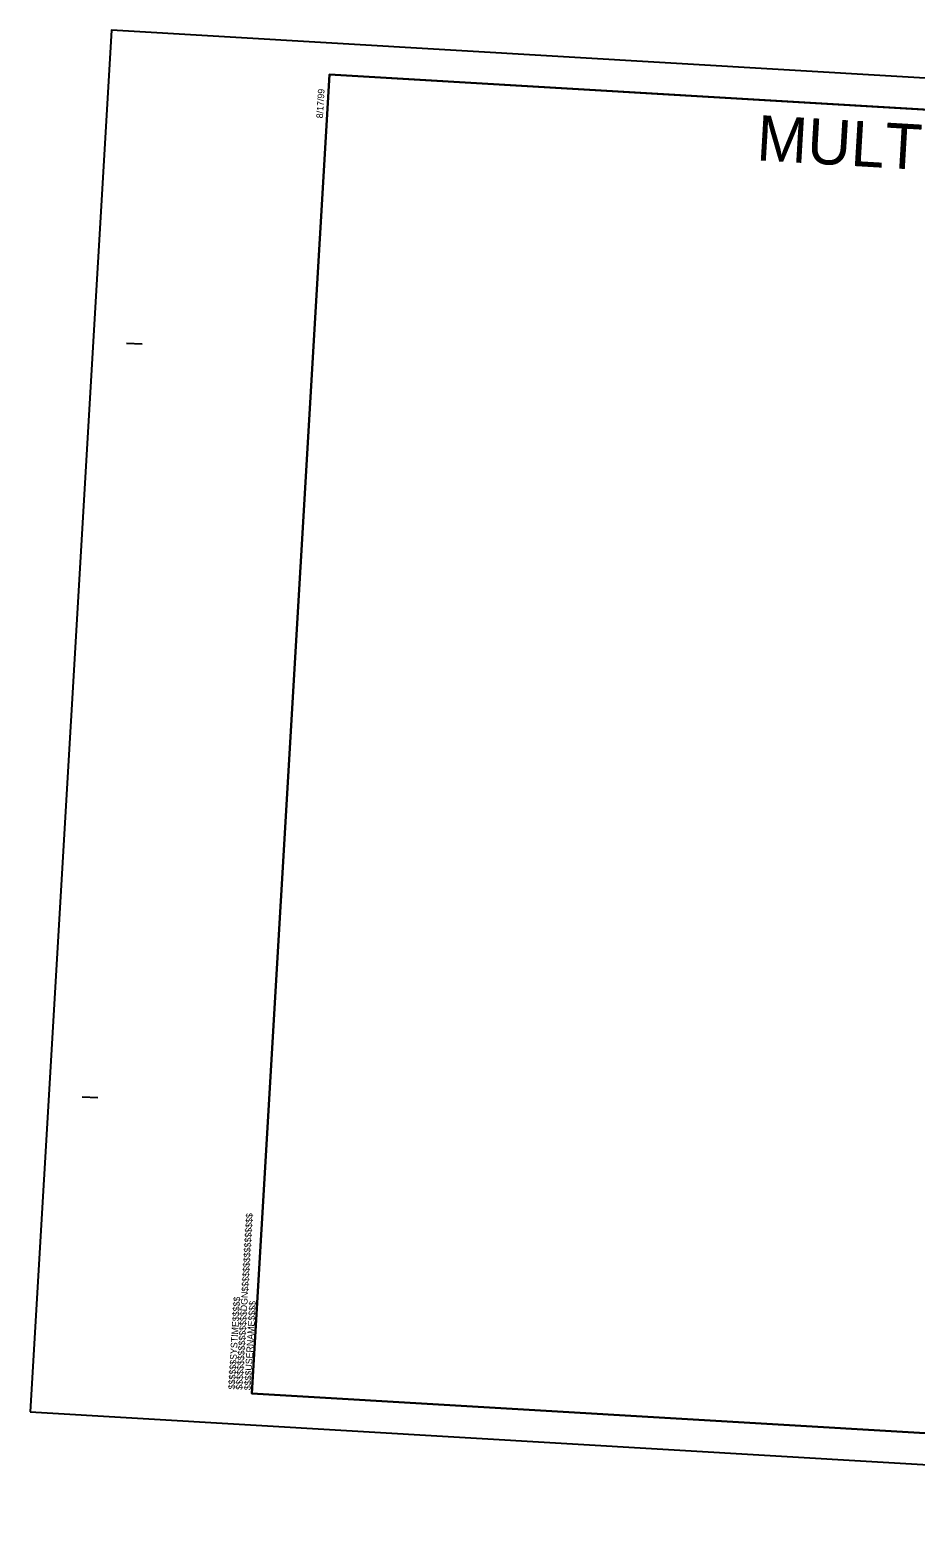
# Model space of a CAD drawing. Extents: x 2011701 to 2013463, y 444552 to 445750.
# Drawn here: x 2011701 to 2012405, y 444552 to 445750 of the extents above; entities that cross this region are included whole.
import ezdxf

# ---------------------------------------------------------------- set-up
doc = ezdxf.new("R2010")
doc.units = 0
for name, color, linetype in [('Prop Dimension', 7, 'Continuous'), ('Sheet Block System Information CELL', 7, 'Continuous'), ('Sheet Clip Boundary CELL', 7, 'Continuous'), ('Sheet Plan And Profile CELL', 7, 'Continuous'), ('Sheet Plot Border Outside CELL', 7, 'Continuous')]:
    doc.layers.add(name, color=color, linetype=linetype)

msp = doc.modelspace()

# ---------------------------------------------------------------- linework, layer by layer
at = {"layer": 'Sheet Block System Information CELL'}
msp.add_line((2011877.5, 444666.9), (2011877.5, 444666.9), dxfattribs=at)
at = {"layer": 'Sheet Clip Boundary CELL'}
msp.add_lwpolyline([(2011939.3, 445715.1), (2013237, 445638.6), (2013226.3, 445456.9), (2013426, 445445.2), (2013374.9, 444578.7), (2011877.5, 444666.9)], close=True, dxfattribs=at)
at = {"layer": 'Sheet Plan And Profile CELL'}
for p, q in [((2011778, 445501.7), (2011790.5, 445501)), ((2011742.7, 444902.8), (2011755.2, 444902.1)), ((2011901.8, 444665.5), (2011901.8, 444665.5)), ((2011901.8, 444665.5), (2011901.8, 444665.5)), ((2011901.8, 444665.5), (2011901.8, 444665.5)), ((2011901.8, 444665.5), (2011901.8, 444665.5)), ((2011901.8, 444665.5), (2011901.8, 444665.5))]:
    msp.add_line(p, q, dxfattribs=at)
msp.add_lwpolyline([(2013436.7, 445626.9), (2011939.3, 445715.1), (2011877.5, 444666.9), (2013374.9, 444578.7)], close=True, dxfattribs=at)
at = {"layer": 'Sheet Plot Border Outside CELL'}
msp.add_lwpolyline([(2011701.4, 444652.3), (2013398.4, 444552.2), (2013463.2, 445650.3), (2011766.1, 445750.4)], close=True, dxfattribs=at)

# ---------------------------------------------------------------- texts
at = {"layer": 'Prop Dimension'}
msp.add_text('MULTI-USE PATH ALIGNMENT', height=36, rotation=356.6264, dxfattribs=at).set_placement((2012278.1, 445647))
at = {"layer": 'Sheet Block System Information CELL'}
for s, p in [('$$$$$$$$$$$$$$$$DGN$$$$$$$$$$$$$$$$', (2011870, 444669.8)), ('$$$$$$SYSTIME$$$$$', (2011864, 444670.1)), ('$$$$USERNAME$$$$', (2011876.6, 444669.4))]:
    msp.add_text(s, height=5.25, rotation=86.6264, dxfattribs=at).set_placement(p)
at = {"layer": 'Sheet Plan And Profile CELL'}
msp.add_text('8/17/99', height=5.25, rotation=86.6264, dxfattribs=at).set_placement((2011934, 445680.2))

doc.saveas('drawing.dxf')
